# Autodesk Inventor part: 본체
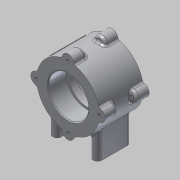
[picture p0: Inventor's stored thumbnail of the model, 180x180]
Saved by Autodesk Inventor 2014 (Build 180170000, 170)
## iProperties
Created: 2015-03
Part Number: 본체
Material: 알루미늄 6061
Document SubType Name: Modeling
Designer: MYHOME
Mass: 450.776 g
Surface Area: 332.745 cm^2
Volume: 166.338 cm^3
Density: 2.71 g/cm^3
Appearance: 알루미늄 - 평지
Author: MYHOME
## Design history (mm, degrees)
sketch "스케치2"
  geometry: C1 r 37 at (0, 0); 1 further point
  constraints: 1 centre point, 1 coincident
  dimensions: "d0" = 74 diameter of C1
extrude "돌출1" new body sketch "스케치2" stored distance "d1" = 52; taper "d2" = 0 deg
sketch "스케치3"
  geometry: C1 r 7 at (-37, 0); C2 r 7 at (0, 37); C3 r 7 at (37, 0); C4 r 7 at (0, -37); A1 r 37 centre (0, 0) between (-37, 0) and (37, 0) reference
  constraints: 4 centre point, 4 point on circle, 3 equal radius, 2 horizontal alignment, 2 vertical alignment
  dimensions: "d3" = 7 radius of C1
extrude "돌출2" join sketch "스케치3" distance "d4" = 15; taper "d5" = 0 deg
fillet "모깎기1" dims "d6" = 3
fillet "모깎기2" dims "d7" = 3
hole "구멍1" diameter "d10" = 42; stored, may be unused: countersink angle "d14" = 90 deg, drill point angle "d16" = 0 deg; dims "d11" = 6, "d12" = 47, "d13" = 22, "d15" = 30, "d17" = 10, "d18" = 10
hole "구멍2" diameter "d21" = 47; stored, may be unused: countersink angle "d25" = 90 deg, drill point angle "d27" = 0 deg; dims "d22" = 6, "d23" = 47, "d24" = 22, "d26" = 22, "d28" = 10, "d29" = 10
sketch "스케치4"
  geometry: A1 r 7 centre (37, 0) between (38.239, -6.889) and (38.239, 6.889) reference; A2 r 7 centre (0, 37) between (6.889, 38.239) and (-6.889, 38.239) reference; A3 r 7 centre (-37, 0) between (-38.239, 6.889) and (-38.239, -6.889) reference; A4 r 7 centre (0, -37) between (-6.889, -38.239) and (6.889, -38.239) reference
hole "구멍3" sketch "스케치4" at (0, -37), (37, 0), (0, 37), (-37, 0) diameter "d30" = 3.242; stored, may be unused: countersink angle "d34" = 90 deg, drill point angle "d36" = 118 deg; dims "d31" = 8, "d32" = 47, "d33" = 22, "d35" = 11
sketch "스케치5"
  geometry: L1 (0, 0)-(0, -45.714); L2 (19, -31.749)-(19, -56); L3 (29, -22.978)-(29, -56); L4 (-19, -31.749)-(-19, -56); L5 (-29, -22.978)-(-29, -56); L6 (-29, -56)-(-19, -56); L7 (19, -56)-(29, -56); A1 r 37 centre (0, 0) between (-35.863, -9.104) and (-9.104, -35.863) reference; A2 r 37 centre (0, 0) between (9.104, -35.863) and (35.863, -9.104) reference
  constraints: 14 end point, 4 parallel, 4 point on circle, 2 perpendicular, 1 collinear, 1 vertical, 2 other
  dimensions: "d37" = 10 distance of L2.end L3.end; "d38" = 38 distance between parallel lines of L2 L4; "d39" = 56 distance from line of L7 L1.start
extrude "돌출3" join sketch "스케치5" stored distance "d40" = 40; taper "d41" = 0 deg
fillet "모깎기3" dims "d42" = 5
sketch "스케치6"
  geometry: L1 (-53, 30)-(-53, 0) reference; L2 (-43, 30)-(-43, 0) reference; A1 r 5 centre (0, 0) between (-5, 0) and (5, 0) reference; A2 r 5 centre (0, 30) between (5, 30) and (-5, 30) reference; A3 r 5 centre (-48, 30) between (-43, 30) and (-53, 30) reference; A4 r 5 centre (-48, 0) between (-53, 0) and (-43, 0) reference; 1 further point
hole "구멍4" sketch "스케치6" at (0, 0), (0, 30), (-48, 0), (-48, 30) diameter "d43" = 4.134; stored, may be unused: countersink angle "d47" = 90 deg, drill point angle "d49" = 118 deg; dims "d44" = 6, "d45" = 47, "d46" = 22, "d48" = 8
sketch "스케치7"
  geometry: L1 (0, 0)-(57.949, 0); L2 (0, 0)-(40.956, 40.956); A1 r 37 centre (0, 0) between (35.863, 9.104) and (9.104, 35.863) reference; 1 further point
  constraints: 4 end point, 1 horizontal, 1 point on circle
  dimensions: "d50" = 45 deg angle of L2 L1
node "작업 평면1"
sketch "스케치8"
  geometry: 2 further points
  constraints: 1 coincident, 1 other
feature "엠보싱1" sketch "스케치8" dims "d51" = 0.5, "d52" = 0
fillet "모깎기4" dims "d53" = 0.3
chamfer "모따기1" distance "d54" = 1; stored, may be unused: second distance "d55" = 2, angle "d56" = 45 deg
fillet "모깎기5" dims "d57" = 3
node "솔리드1"
mirror "대칭1"
mirror "대칭2"
node "투영된 루프1"
